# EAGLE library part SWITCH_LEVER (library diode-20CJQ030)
ALPS's HORIZONTAL TYPE SEESAW AND PUSH OPERATION SWITCHES SLLB Series Features: Rating: 10mA @ 5VDC Lever/Push function operating force: 0.65±0.3N/2±1N Operating life: 100,000 cycles For selecting menus of PDA's, mobile phones, laptop computers, and electronic organizers For selecting menus of remote controllers Single knob allows CW, CCW, and push operations Lever Color: Black except for SLLB120200 and SLLB220200 which are gray. Please send any comments to: messi@users.sourceforge.net
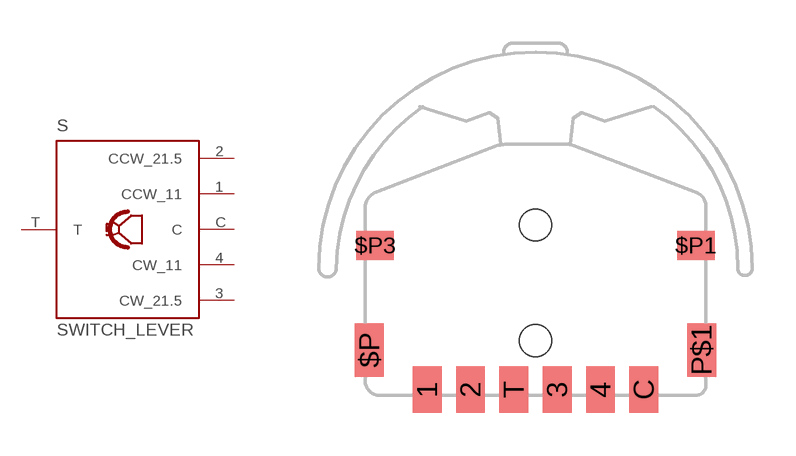
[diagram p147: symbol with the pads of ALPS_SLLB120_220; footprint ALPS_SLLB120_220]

Designator prefix S

## SWITCH_LEVER  [ALPS_SLLB120_220]
1  CCW_11  out
2  CCW_21.5  out
3  CW_21.5  out
4  CW_11  out
C  C  out
T  T  in

## Footprint ALPS_SLLB120_220 (pad centres in mm)
ALPS's Lever and Push Operation Switch SLLB Series
smd 1 x 1.6: 1 -3.75,-3.7; 2 -2.25,-3.7; 3 0.75,-3.7; 4 2.25,-3.7; C 3.75,-3.7; T -0.75,-3.7
smd 1 x 1.85: $P -5.75,-2.325; P$1 5.75,-2.325
smd 1.3 x 1: $P1 5.55,1.3; $P3 -5.55,1.3
hole 1.1 at 0,2
hole 1.1 at 0,-2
